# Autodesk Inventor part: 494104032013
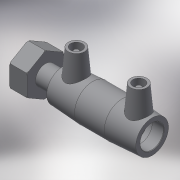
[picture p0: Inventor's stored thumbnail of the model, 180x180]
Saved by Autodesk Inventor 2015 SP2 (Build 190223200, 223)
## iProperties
Created: 2017-06
Part Number: 494104032013
Material: Generic
Description: PLASSON FEMALE FREE NUT TRANSITION COUPLER 32-1"
Document SubType Name: Modeling
Designer: KIM
Mass: 55.0731 g
Surface Area: 148.067 cm^2
Volume: 55.0731 cm^3
Density: 1 g/cm^3
Appearance: Default
Author: KIM
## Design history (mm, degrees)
derived "494104.ipt"
feature "Solid1::494104.ipt"
tag "TaggingFeature1"
body "Solid1"
other parameters: "d0" = 88, "d1" = 32, "d2" = 44, "d3" = 42, "d4" = 29.33333, "d5" = 39.6, "d6" = 30.4, "d7" = 32, "d8" = 168 deg, "d10" = 16.8, "d11" = 5.6, "d29" = 42, "d30" = 14, "d31" = 30.8, "d34" = 5 deg, "d41" = 4, "d42" = 14, "d43" = 0, "d48" = 3, "d49" = 0, "d55" = 36, "d57" = 23, "d80" = 0.64, "d83" = 18, "d84" = 11.88, "d85" = 1.188, "d86" = 31.1616, "d87" = 38.952, "d88" = 58.428, "d89" = 44, "d90" = 1.16856, "d94" = 0, "d95" = 1.188, "d96" = 27.2664, "d_" = 32, "L_" = 124, "L_1" = 42, "D_1" = 44, "A_" = 42, "d_2" = 12, "L_2" = 36, "D_" = 23, "G_" = 38.952
